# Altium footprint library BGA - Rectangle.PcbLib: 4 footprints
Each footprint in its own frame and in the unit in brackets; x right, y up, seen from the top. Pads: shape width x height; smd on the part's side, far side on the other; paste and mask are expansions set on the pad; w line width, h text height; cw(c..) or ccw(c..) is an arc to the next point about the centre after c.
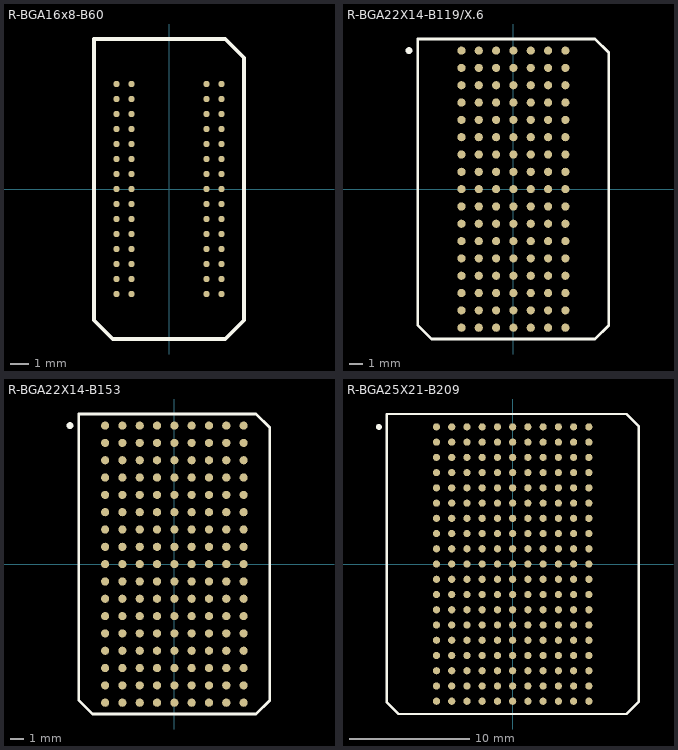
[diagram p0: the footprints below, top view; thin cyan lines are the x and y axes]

## R-BGA16x8-B60 [mm]
pads (60):
  round 0.33 smd: A1(-2.8,5.6) A2(-2,5.6) A7(2,5.6) A8(2.8,5.6) B1(-2.8,4.8) B2(-2,4.8) B7(2,4.8) B8(2.8,4.8) C1(-2.8,4) C2(-2,4) C7(2,4) C8(2.8,4) D1(-2.8,3.2) D2(-2,3.2) D7(2,3.2) D8(2.8,3.2) E1(-2.8,2.4) E2(-2,2.4) E7(2,2.4) E8(2.8,2.4) F1(-2.8,1.6) F2(-2,1.6) F7(2,1.6) F8(2.8,1.6) G1(-2.8,0.8) G2(-2,0.8) G7(2,0.8) G8(2.8,0.8) H1(-2.8,0) H2(-2,0) H7(2,0) H8(2.8,0) J1(-2.8,-0.8) J2(-2,-0.8) J7(2,-0.8) J8(2.8,-0.8) K1(-2.8,-1.6) K2(-2,-1.6) K7(2,-1.6) K8(2.8,-1.6) L1(-2.8,-2.4) L2(-2,-2.4) L7(2,-2.4) L8(2.8,-2.4) M1(-2.8,-3.2) M2(-2,-3.2) M7(2,-3.2) M8(2.8,-3.2) N1(-2.8,-4) N2(-2,-4) N7(2,-4) N8(2.8,-4) P1(-2.8,-4.8) P2(-2,-4.8) P7(2,-4.8) P8(2.8,-4.8) R1(-2.8,-5.6) R2(-2,-5.6) R7(2,-5.6) R8(2.8,-5.6)
Top Overlay:
  lines w0.2: -4,-7 -4,8 3,8 4,7 4,-7 3,-8 -3,-8 -4,-7

## R-BGA22X14-B119/X.6 [mm]
pads (119):
  round 0.6 smd: A1(-3.81,10.16) A2(-2.54,10.16) A3(-1.27,10.16) A4(0,10.16) A5(1.27,10.16) A6(2.54,10.16) A7(3.81,10.16) B1(-3.81,8.89) B2(-2.54,8.89) B3(-1.27,8.89) B4(0,8.89) B5(1.27,8.89) B6(2.54,8.89) B7(3.81,8.89) C1(-3.81,7.62) C2(-2.54,7.62) C3(-1.27,7.62) C4(0,7.62) C5(1.27,7.62) C6(2.54,7.62) C7(3.81,7.62) D1(-3.81,6.35) D2(-2.54,6.35) D3(-1.27,6.35) D4(0,6.35) D5(1.27,6.35) D6(2.54,6.35) D7(3.81,6.35) E1(-3.81,5.08) E2(-2.54,5.08) E3(-1.27,5.08) E4(0,5.08) E5(1.27,5.08) E6(2.54,5.08) E7(3.81,5.08) F1(-3.81,3.81) F2(-2.54,3.81) F3(-1.27,3.81) F4(0,3.81) F5(1.27,3.81) F6(2.54,3.81) F7(3.81,3.81) G1(-3.81,2.54) G2(-2.54,2.54) G3(-1.27,2.54) G4(0,2.54) G5(1.27,2.54) G6(2.54,2.54) G7(3.81,2.54) H1(-3.81,1.27) H2(-2.54,1.27) H3(-1.27,1.27) H4(0,1.27) H5(1.27,1.27) H6(2.54,1.27) H7(3.81,1.27) J1(-3.81,0) J2(-2.54,0) J3(-1.27,0) J4(0,0) J5(1.27,0) J6(2.54,0) J7(3.81,0) K1(-3.81,-1.27) K2(-2.54,-1.27) K3(-1.27,-1.27) K4(0,-1.27) K5(1.27,-1.27) K6(2.54,-1.27) K7(3.81,-1.27) L1(-3.81,-2.54) L2(-2.54,-2.54) L3(-1.27,-2.54) L4(0,-2.54) L5(1.27,-2.54) L6(2.54,-2.54) L7(3.81,-2.54) M1(-3.81,-3.81) M2(-2.54,-3.81) M3(-1.27,-3.81) M4(0,-3.81) M5(1.27,-3.81) M6(2.54,-3.81) M7(3.81,-3.81) N1(-3.81,-5.08) N2(-2.54,-5.08) N3(-1.27,-5.08) N4(0,-5.08) N5(1.27,-5.08) N6(2.54,-5.08) N7(3.81,-5.08) P1(-3.81,-6.35) P2(-2.54,-6.35) P3(-1.27,-6.35) P4(0,-6.35) P5(1.27,-6.35) P6(2.54,-6.35) P7(3.81,-6.35) R1(-3.81,-7.62) R2(-2.54,-7.62) R3(-1.27,-7.62) R4(0,-7.62) R5(1.27,-7.62) R6(2.54,-7.62) R7(3.81,-7.62) T1(-3.81,-8.89) T2(-2.54,-8.89) T3(-1.27,-8.89) T4(0,-8.89) T5(1.27,-8.89) T6(2.54,-8.89) T7(3.81,-8.89) U1(-3.81,-10.16) U2(-2.54,-10.16) U3(-1.27,-10.16) U4(0,-10.16) U5(1.27,-10.16) U6(2.54,-10.16) U7(3.81,-10.16)
Top Overlay:
  circle w0.25: c-7.66,10.16 r0.125
  lines w0.2: -7.01,-9.99 -7.01,11.01 5.99,11.01 6.99,10.01 6.99,-9.99 5.99,-10.99 -6.01,-10.99 -7.01,-9.99

## R-BGA22X14-B153 [mm]
pads (153):
  round 0.6 smd: A1(-5.08,10.16) A2(-3.81,10.16) A3(-2.54,10.16) A4(-1.27,10.16) A5(0,10.16) A6(1.27,10.16) A7(2.54,10.16) A8(3.81,10.16) A9(5.08,10.16) B1(-5.08,8.89) B2(-3.81,8.89) B3(-2.54,8.89) B4(-1.27,8.89) B5(0,8.89) B6(1.27,8.89) B7(2.54,8.89) B8(3.81,8.89) B9(5.08,8.89) C1(-5.08,7.62) C2(-3.81,7.62) C3(-2.54,7.62) C4(-1.27,7.62) C5(0,7.62) C6(1.27,7.62) C7(2.54,7.62) C8(3.81,7.62) C9(5.08,7.62) D1(-5.08,6.35) D2(-3.81,6.35) D3(-2.54,6.35) D4(-1.27,6.35) D5(0,6.35) D6(1.27,6.35) D7(2.54,6.35) D8(3.81,6.35) D9(5.08,6.35) E1(-5.08,5.08) E2(-3.81,5.08) E3(-2.54,5.08) E4(-1.27,5.08) E5(0,5.08) E6(1.27,5.08) E7(2.54,5.08) E8(3.81,5.08) E9(5.08,5.08) F1(-5.08,3.81) F2(-3.81,3.81) F3(-2.54,3.81) F4(-1.27,3.81) F5(0,3.81) F6(1.27,3.81) F7(2.54,3.81) F8(3.81,3.81) F9(5.08,3.81) G1(-5.08,2.54) G2(-3.81,2.54) G3(-2.54,2.54) G4(-1.27,2.54) G5(0,2.54) G6(1.27,2.54) G7(2.54,2.54) G8(3.81,2.54) G9(5.08,2.54) H1(-5.08,1.27) H2(-3.81,1.27) H3(-2.54,1.27) H4(-1.27,1.27) H5(0,1.27) H6(1.27,1.27) H7(2.54,1.27) H8(3.81,1.27) H9(5.08,1.27) J1(-5.08,0) J2(-3.81,0) J3(-2.54,0) J4(-1.27,0) J5(0,0) J6(1.27,0) J7(2.54,0) J8(3.81,0) J9(5.08,0) K1(-5.08,-1.27) K2(-3.81,-1.27) K3(-2.54,-1.27) K4(-1.27,-1.27) K5(0,-1.27) K6(1.27,-1.27) K7(2.54,-1.27) K8(3.81,-1.27) K9(5.08,-1.27) L1(-5.08,-2.54) L2(-3.81,-2.54) L3(-2.54,-2.54) L4(-1.27,-2.54) L5(0,-2.54) L6(1.27,-2.54) L7(2.54,-2.54) L8(3.81,-2.54) L9(5.08,-2.54) M1(-5.08,-3.81) M2(-3.81,-3.81) M3(-2.54,-3.81) M4(-1.27,-3.81) M5(0,-3.81) M6(1.27,-3.81) M7(2.54,-3.81) M8(3.81,-3.81) M9(5.08,-3.81) N1(-5.08,-5.08) N2(-3.81,-5.08) N3(-2.54,-5.08) N4(-1.27,-5.08) N5(0,-5.08) N6(1.27,-5.08) N7(2.54,-5.08) N8(3.81,-5.08) N9(5.08,-5.08) P1(-5.08,-6.35) P2(-3.81,-6.35) P3(-2.54,-6.35) P4(-1.27,-6.35) P5(0,-6.35) P6(1.27,-6.35) P7(2.54,-6.35) P8(3.81,-6.35) P9(5.08,-6.35) R1(-5.08,-7.62) R2(-3.81,-7.62) R3(-2.54,-7.62) R4(-1.27,-7.62) R5(0,-7.62) R6(1.27,-7.62) R7(2.54,-7.62) R8(3.81,-7.62) R9(5.08,-7.62) T1(-5.08,-8.89) T2(-3.81,-8.89) T3(-2.54,-8.89) T4(-1.27,-8.89) T5(0,-8.89) T6(1.27,-8.89) T7(2.54,-8.89) T8(3.81,-8.89) T9(5.08,-8.89) U1(-5.08,-10.16) U2(-3.81,-10.16) U3(-2.54,-10.16) U4(-1.27,-10.16) U5(0,-10.16) U6(1.27,-10.16) U7(2.54,-10.16) U8(3.81,-10.16) U9(5.08,-10.16)
Top Overlay:
  circle w0.25: c-7.655,10.16 r0.125
  lines w0.2: -7.005,-9.99 -7.005,11.01 5.995,11.01 6.995,10.01 6.995,-9.99 5.995,-10.99 -6.005,-10.99 -7.005,-9.99

## R-BGA25X21-B209 [mm]
pads (209):
  round 0.6 smd: A1(-6.35,11.43) A2(-5.08,11.43) A3(-3.81,11.43) A4(-2.54,11.43) A5(-1.27,11.43) A6(0,11.43) A7(1.27,11.43) A8(2.54,11.43) A9(3.81,11.43) A10(5.08,11.43) A11(6.35,11.43) B1(-6.35,10.16) B2(-5.08,10.16) B3(-3.81,10.16) B4(-2.54,10.16) B5(-1.27,10.16) B6(0,10.16) B7(1.27,10.16) B8(2.54,10.16) B9(3.81,10.16) B10(5.08,10.16) B11(6.35,10.16) C1(-6.35,8.89) C2(-5.08,8.89) C3(-3.81,8.89) C4(-2.54,8.89) C5(-1.27,8.89) C6(0,8.89) C7(1.27,8.89) C8(2.54,8.89) C9(3.81,8.89) C10(5.08,8.89) C11(6.35,8.89) D1(-6.35,7.62) D2(-5.08,7.62) D3(-3.81,7.62) D4(-2.54,7.62) D5(-1.27,7.62) D6(0,7.62) D7(1.27,7.62) D8(2.54,7.62) D9(3.81,7.62) D10(5.08,7.62) D11(6.35,7.62) E1(-6.35,6.35) E2(-5.08,6.35) E3(-3.81,6.35) E4(-2.54,6.35) E5(-1.27,6.35) E6(0,6.35) E7(1.27,6.35) E8(2.54,6.35) E9(3.81,6.35) E10(5.08,6.35) E11(6.35,6.35) F1(-6.35,5.08) F2(-5.08,5.08) F3(-3.81,5.08) F4(-2.54,5.08) F5(-1.27,5.08) F6(0,5.08) F7(1.27,5.08) F8(2.54,5.08) F9(3.81,5.08) F10(5.08,5.08) F11(6.35,5.08) G1(-6.35,3.81) G2(-5.08,3.81) G3(-3.81,3.81) G4(-2.54,3.81) G5(-1.27,3.81) G6(0,3.81) G7(1.27,3.81) G8(2.54,3.81) G9(3.81,3.81) G10(5.08,3.81) G11(6.35,3.81) H1(-6.35,2.54) H2(-5.08,2.54) H3(-3.81,2.54) H4(-2.54,2.54) H5(-1.27,2.54) H6(0,2.54) H7(1.27,2.54) H8(2.54,2.54) H9(3.81,2.54) H10(5.08,2.54) H11(6.35,2.54) J1(-6.35,1.27) J2(-5.08,1.27) J3(-3.81,1.27) J4(-2.54,1.27) J5(-1.27,1.27) J6(0,1.27) J7(1.27,1.27) J8(2.54,1.27) J9(3.81,1.27) J10(5.08,1.27) J11(6.35,1.27) K1(-6.35,0) K2(-5.08,0) K3(-3.81,0) K4(-2.54,0) K5(-1.27,0) K6(0,0) K7(1.27,0) K8(2.54,0) K9(3.81,0) K10(5.08,0) K11(6.35,0) L1(-6.35,-1.27) L2(-5.08,-1.27) L3(-3.81,-1.27) L4(-2.54,-1.27) L5(-1.27,-1.27) L6(0,-1.27) L7(1.27,-1.27) L8(2.54,-1.27) L9(3.81,-1.27) L10(5.08,-1.27) L11(6.35,-1.27) M1(-6.35,-2.54) M2(-5.08,-2.54) M3(-3.81,-2.54) M4(-2.54,-2.54) M5(-1.27,-2.54) M6(0,-2.54) M7(1.27,-2.54) M8(2.54,-2.54) M9(3.81,-2.54) M10(5.08,-2.54) M11(6.35,-2.54) N1(-6.35,-3.81) N2(-5.08,-3.81) N3(-3.81,-3.81) N4(-2.54,-3.81) N5(-1.27,-3.81) N6(0,-3.81) N7(1.27,-3.81) N8(2.54,-3.81) N9(3.81,-3.81) N10(5.08,-3.81) N11(6.35,-3.81) P1(-6.35,-5.08) P2(-5.08,-5.08) P3(-3.81,-5.08) P4(-2.54,-5.08) P5(-1.27,-5.08) P6(0,-5.08) P7(1.27,-5.08) P8(2.54,-5.08) P9(3.81,-5.08) P10(5.08,-5.08) P11(6.35,-5.08) R1(-6.35,-6.35) R2(-5.08,-6.35) R3(-3.81,-6.35) R4(-2.54,-6.35) R5(-1.27,-6.35) R6(0,-6.35) R7(1.27,-6.35) R8(2.54,-6.35) R9(3.81,-6.35) R10(5.08,-6.35) R11(6.35,-6.35) T1(-6.35,-7.62) T2(-5.08,-7.62) T3(-3.81,-7.62) T4(-2.54,-7.62) T5(-1.27,-7.62) T6(0,-7.62) T7(1.27,-7.62) T8(2.54,-7.62) T9(3.81,-7.62) T10(5.08,-7.62) T11(6.35,-7.62) U1(-6.35,-8.89) U2(-5.08,-8.89) U3(-3.81,-8.89) U4(-2.54,-8.89) U5(-1.27,-8.89) U6(0,-8.89) U7(1.27,-8.89) U8(2.54,-8.89) U9(3.81,-8.89) U10(5.08,-8.89) U11(6.35,-8.89) V1(-6.35,-10.16) V2(-5.08,-10.16) V3(-3.81,-10.16) V4(-2.54,-10.16) V5(-1.27,-10.16) V6(0,-10.16) V7(1.27,-10.16) V8(2.54,-10.16) V9(3.81,-10.16) V10(5.08,-10.16) V11(6.35,-10.16) W1(-6.35,-11.43) W2(-5.08,-11.43) W3(-3.81,-11.43) W4(-2.54,-11.43) W5(-1.27,-11.43) W6(0,-11.43) W7(1.27,-11.43) W8(2.54,-11.43) W9(3.81,-11.43) W10(5.08,-11.43) W11(6.35,-11.43)
Top Overlay:
  circle w0.25: c-11.15,11.43 r0.125
  lines w0.2: -10.5,-11.495 -10.5,12.505 9.5,12.505 10.5,11.505 10.5,-11.495 9.5,-12.495 -9.5,-12.495 -10.5,-11.495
